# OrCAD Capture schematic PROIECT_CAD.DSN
size A4
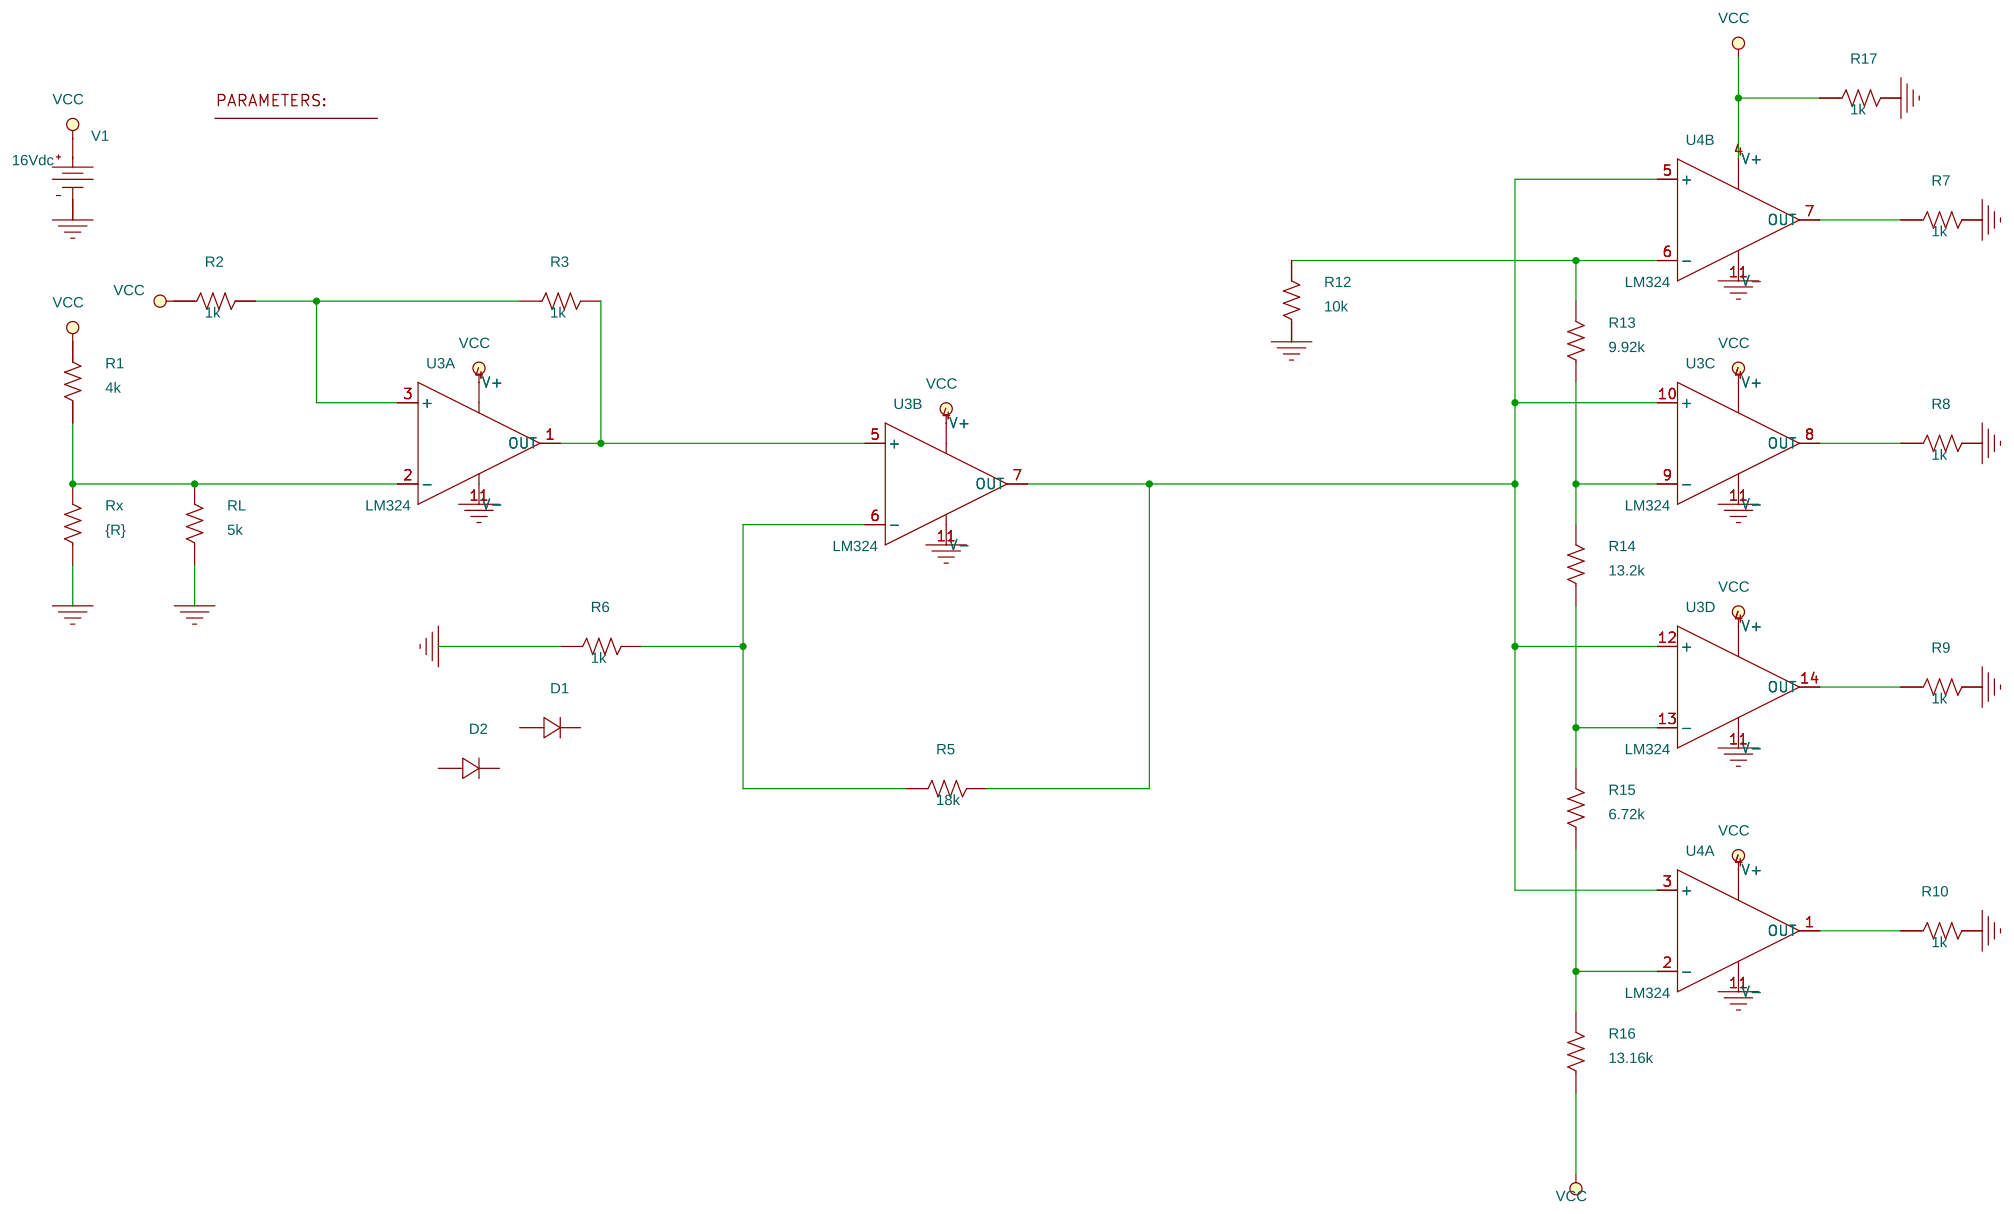
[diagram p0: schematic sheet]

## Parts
1  PARAM
D1  Dbreak
D2  Dbreak
R1  4k  [AX/RC05]
R2  1k  [AX/RC05]
R3  1k  [AX/RC05]
R5  18k  [AX/RC05]
R6  1k  [AX/RC05]
R7  1k  [AX/RC05]
R8  1k  [AX/RC05]
R9  1k  [AX/RC05]
R10  1k  [AX/RC05]
R12  10k  [AX/RC05]
R13  9.92k  [AX/RC05]
R14  13.2k  [AX/RC05]
R15  6.72k  [AX/RC05]
R16  13.16k  [AX/RC05]
R17  1k  [AX/RC05]
RL  5k  [AX/RC05]
Rx  {R}  [AX/RC05]
U3  LM324  [DIP.100/14/W.300/L.800]  (sections A,B,C,D)
U4  LM324  [DIP.100/14/W.300/L.800]  (sections A,B)
V1  VDC

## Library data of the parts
1 = PARAM: R: 20k
D1 D2 = Dbreak
R1-R3 R5-R10 R12-R17 RL Rx = R
U3 U4 = LM324
V1 = VDC: DC: 16Vdc

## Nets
VCC: R1.2 R2.1 R16.1 R17.1 U3.4(V+) U4.4(V+) V1.0(+)
0: R6.1 R7.2 R8.2 R9.2 R10.2 R12.1 R17.2 RL.1 Rx.1 U3.11(V-) U4.11(V-) V1.1(-)
N00141: R1.1 RL.2 Rx.2 U3.2(-)
N05181: R2.2 R3.1 U3.3(+)
N05313: R3.2 U3.1(OUT) U3.5(+)
N05394: R5.1 R6.2 U3.6(-)
N05435: R5.2 U3.7(OUT) U3.10(+) U3.12(+) U4.3(+) U4.5(+)
N06303: R7.1 U4.7(OUT)
N06314: R8.1 U3.8(OUT)
N06318: R9.1 U3.14(OUT)
N06454: R12.2 R13.2 U4.6(-)
N06471: R13.1 R14.2 U3.9(-)
N06484: R14.1 R15.2 U3.13(-)
N06499: R15.1 R16.2 U4.2(-)
N10607: R10.1 U4.1(OUT)

Not connected (* = marked no-connect by the designer): D1 0(1) 1(2); D2 0(1) 1(2)
